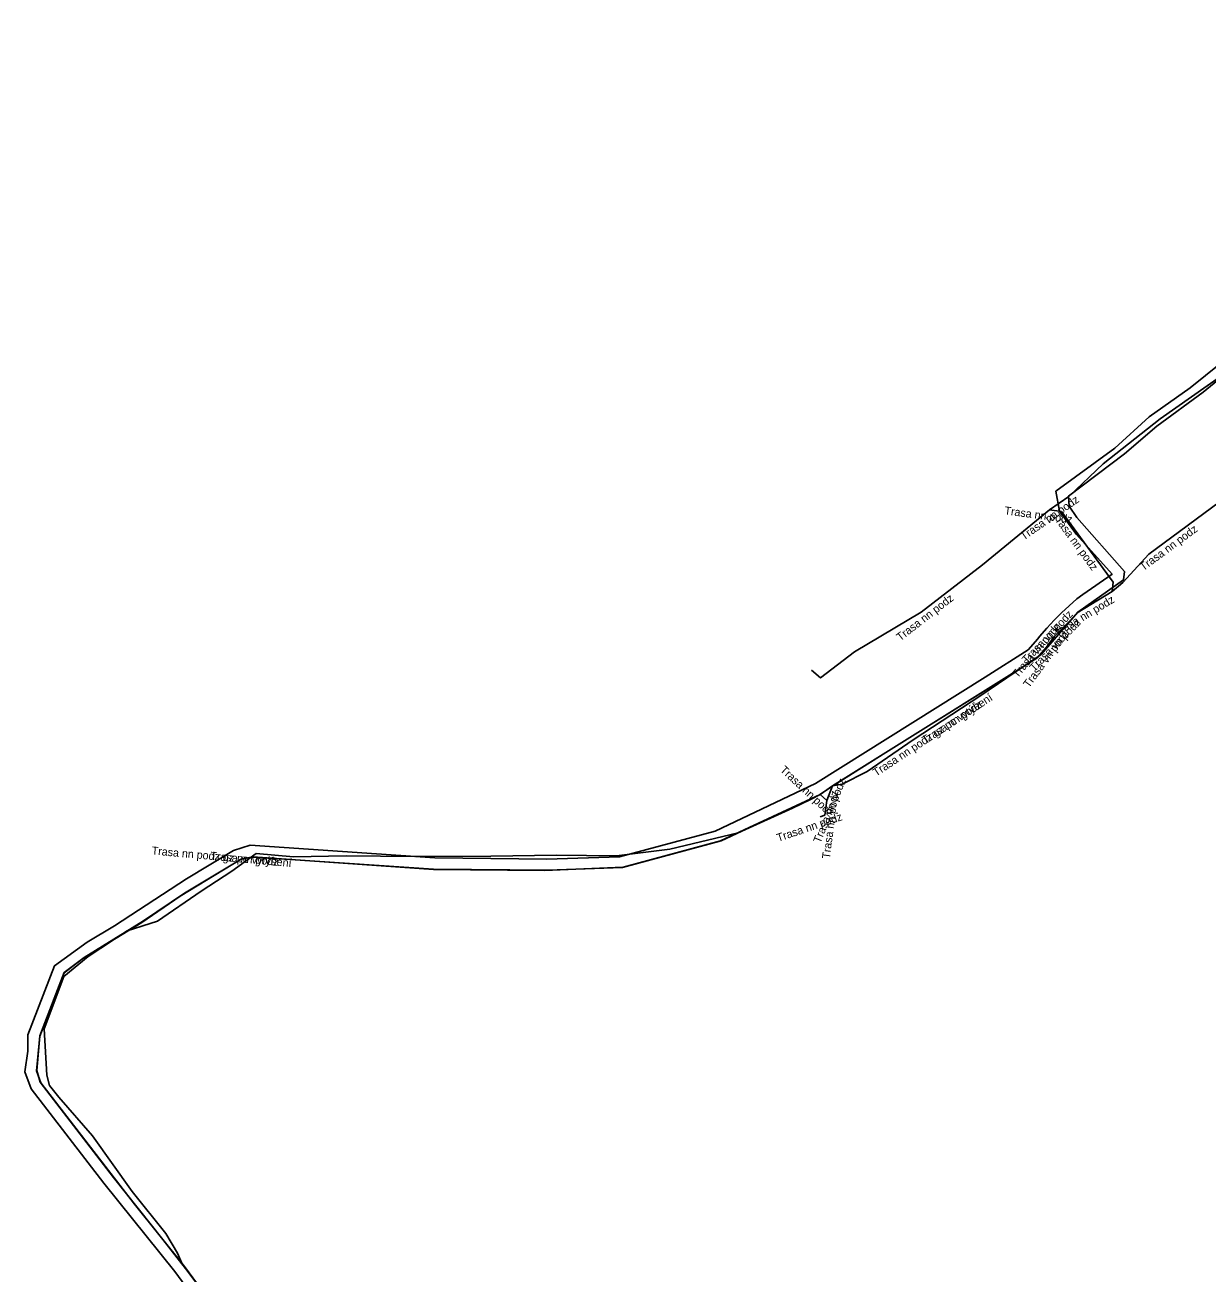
# Model space of a CAD drawing. Extents: x -703240 to -702678, y -1007635 to -1007322.
# Drawn here: x -702904.4 to -702830.5, y -1007513.3 to -1007435.3 of the extents above; entities that cross this region are included whole.
import ezdxf

# ---------------------------------------------------------------- set-up
doc = ezdxf.new("R2010")
doc.units = 0
for name, color, linetype in [('Popiskový text - Ostatní atributy Trasy', 7, 'Continuous'), ('Spojnice NN', 7, 'Continuous'), ('Spojnice VN', 7, 'Continuous')]:
    doc.layers.add(name, color=color, linetype=linetype)

msp = doc.modelspace()

# ---------------------------------------------------------------- linework, layer by layer
at = {"layer": 'Spojnice NN'}
for points in [[(-702839.14, -1007464.79), (-702836.99, -1007462.74), (-702833.42, -1007459.94), (-702829.52, -1007457.19), (-702825.59, -1007453.79), (-702823.26, -1007451.11), (-702819.97, -1007448.18), (-702814.78, -1007443.62), (-702812.71, -1007442.11), (-702810.87, -1007440.57), (-702807.36, -1007437.54), (-702804.792, -1007435.331)], [(-702839.14, -1007464.79), (-702836.99, -1007462.74), (-702833.42, -1007459.94), (-702829.52, -1007457.19), (-702825.59, -1007453.79), (-702823.26, -1007451.11), (-702819.97, -1007448.18), (-702814.78, -1007443.62), (-702812.71, -1007442.11), (-702810.87, -1007440.57), (-702807.36, -1007437.54), (-702804.792, -1007435.331)], [(-702836.43, -1007470.73), (-702835.75, -1007470.17), (-702834.13, -1007468.4), (-702829.26, -1007464.8), (-702827.98, -1007463.68)], [(-702840.34, -1007465.63), (-702839.14, -1007464.79)], [(-702840.34, -1007465.63), (-702844.53, -1007469.06), (-702848.35, -1007472.01), (-702852.53, -1007474.49), (-702854.65, -1007476.12), (-702855.22, -1007475.65)], [(-702839.6, -1007465.73), (-702840.34, -1007465.63)], [(-702836.43, -1007470.73), (-702836.36, -1007470.15), (-702839.6, -1007465.73)], [(-702838.62, -1007472.05), (-702836.43, -1007470.73)], [(-702853.89, -1007482.87), (-702853.3, -1007482.76), (-702851.73, -1007481.97), (-702848.86, -1007480), (-702844.63, -1007477.22), (-702840.87, -1007474.67), (-702838.568, -1007472.016)], [(-702853.89, -1007482.87), (-702853.3, -1007482.76), (-702851.73, -1007481.97), (-702848.86, -1007480), (-702844.63, -1007477.22), (-702840.87, -1007474.67), (-702838.568, -1007472.016)], [(-702854.26, -1007483.78), (-702853.89, -1007482.87)], [(-702894.55, -1007512.69), (-702894.82, -1007512.06), (-702895.56, -1007510.83), (-702897.66, -1007508.21), (-702900.14, -1007504.74), (-702902.23, -1007502.31), (-702902.82, -1007501.6), (-702902.99, -1007500.95), (-702903.16, -1007498.04), (-702901.92, -1007494.78), (-702900.4, -1007493.52), (-702897.98, -1007491.93), (-702896.07, -1007491.32), (-702893.35, -1007489.44), (-702891.44, -1007488.19), (-702889.91, -1007487.09), (-702887.58, -1007487.3), (-702884.28, -1007487.25), (-702880, -1007487.29), (-702875.24, -1007487.27), (-702871.14, -1007487.2), (-702867.4, -1007487.25), (-702864.06, -1007486.82), (-702859.79, -1007485.81), (-702856.4, -1007484.26), (-702855.28, -1007483.73), (-702854.67, -1007483.4)], [(-702894.55, -1007512.69), (-702894.82, -1007512.06), (-702895.56, -1007510.83), (-702897.66, -1007508.21), (-702900.14, -1007504.74), (-702902.23, -1007502.31), (-702902.82, -1007501.6), (-702902.99, -1007500.95), (-702903.16, -1007498.04), (-702901.92, -1007494.78), (-702900.4, -1007493.52), (-702897.98, -1007491.93), (-702896.07, -1007491.32), (-702893.35, -1007489.44), (-702891.44, -1007488.19), (-702889.91, -1007487.09), (-702887.58, -1007487.3), (-702884.28, -1007487.25), (-702880, -1007487.29), (-702875.24, -1007487.27), (-702871.14, -1007487.2), (-702867.4, -1007487.25), (-702864.06, -1007486.82), (-702859.79, -1007485.81), (-702856.4, -1007484.26), (-702855.28, -1007483.73), (-702854.67, -1007483.4)], [(-702854.67, -1007483.4), (-702854.26, -1007483.78)], [(-702854.26, -1007483.78), (-702854.375, -1007484.698)], [(-702854.661, -1007484.795), (-702854.375, -1007484.698)]]:
    msp.add_lwpolyline(points, dxfattribs=at)
at = {"layer": 'Spojnice VN'}
for points in [[(-702827.827, -1007455.01), (-702831.56, -1007458.012), (-702834.103, -1007459.821), (-702836.257, -1007461.777), (-702839.953, -1007464.459), (-702839.722, -1007465.716), (-702838.646, -1007467.157), (-702836.43, -1007469.652), (-702838.258, -1007470.92), (-702838.624, -1007471.186), (-702839.593, -1007472.052)], [(-702827.331, -1007455.484), (-702830.736, -1007458.277), (-702833.625, -1007460.39), (-702835.657, -1007462.134), (-702839.144, -1007464.761), (-702839.105, -1007465.389), (-702838.629, -1007466.1), (-702835.663, -1007469.469), (-702835.72, -1007470.002), (-702838.568, -1007472.016), (-702839.1, -1007472.57)], [(-702839.593, -1007472.052), (-702840.05, -1007472.519), (-702840.517, -1007473.013)], [(-702840.517, -1007473.013), (-702840.955, -1007473.529), (-702841.076, -1007473.679)], [(-702839.1, -1007472.57), (-702840.02, -1007473.52)], [(-702840.02, -1007473.52), (-702839.1, -1007472.57)], [(-702841.076, -1007473.679), (-702841.668, -1007474.363), (-702844.359, -1007476.086), (-702854.952, -1007482.726), (-702861.226, -1007485.69), (-702867.214, -1007487.307), (-702871.752, -1007487.458), (-702878.755, -1007487.363), (-702890.287, -1007486.584), (-702891.328, -1007486.908), (-702894.272, -1007488.676), (-702898.755, -1007491.604), (-702900.467, -1007492.628), (-702902.51, -1007494.113), (-702904.183, -1007498.427), (-702904.183, -1007499.436), (-702904.356, -1007500.731), (-702903.972, -1007501.796), (-702899.43, -1007507.686), (-702894.987, -1007513.213), (-702893.329, -1007515.479)], [(-702840.02, -1007473.52), (-702840.53, -1007474.21)], [(-702840.53, -1007474.21), (-702840.02, -1007473.52)], [(-702840.53, -1007474.21), (-702841.172, -1007474.915), (-702850.572, -1007480.791), (-702854.007, -1007482.956), (-702854.719, -1007483.432), (-702860.857, -1007486.301), (-702867.017, -1007487.966), (-702871.682, -1007488.146), (-702878.823, -1007488.079), (-702887.775, -1007487.471), (-702890.228, -1007487.319), (-702890.883, -1007487.472), (-702894.663, -1007489.77), (-702897.057, -1007491.404), (-702900.737, -1007493.661), (-702901.907, -1007494.55), (-702903.427, -1007498.513), (-702903.629, -1007500.665), (-702903.361, -1007501.422), (-702897.51, -1007509.006), (-702894.394, -1007512.891), (-702893.276, -1007514.395)], [(-702893.31, -1007514.37), (-702894.32, -1007513.02), (-702895.75, -1007511.22), (-702898.83, -1007507.33), (-702903.41, -1007501.39), (-702903.62, -1007500.66), (-702903.43, -1007498.49), (-702901.91, -1007494.54), (-702900.66, -1007493.6), (-702896.94, -1007491.3), (-702894.38, -1007489.58), (-702890.85, -1007487.45), (-702890.12, -1007487.31), (-702878.82, -1007488.1), (-702871.89, -1007488.15), (-702866.98, -1007487.95), (-702860.89, -1007486.31), (-702854.67, -1007483.4), (-702853.89, -1007482.87), (-702841.14, -1007474.9), (-702840.53, -1007474.21)]]:
    msp.add_lwpolyline(points, dxfattribs=at)

# ---------------------------------------------------------------- texts
at = {"layer": 'Popiskový text - Ostatní atributy Trasy'}
for s, rotation, p in [('Trasa nn podz', 34.99202, (-702841.946, -1007467.548)), ('Trasa nn podz', 352.30395, (-702843.177, -1007465.902)), ('Trasa nn podz', 306.2426, (-702840.193, -1007466.021)), ('Trasa nn podz', 36.47254, (-702834.475, -1007469.463)), ('Trasa nn podz', 37.67716, (-702849.665, -1007473.847)), ('Trasa nn podz', 31.07904, (-702839.886, -1007473.572)), ('Trasa vn podz', 46.60934, (-702841.749, -1007475.262)), ('Trasa vn podz', 49.67416, (-702842.339, -1007476.164)), ('Trasa vn podz', 45.9191, (-702841.283, -1007475.758)), ('Trasa vn podz', 45.9191, (-702841.283, -1007475.758)), ('Trasa vn podz', 53.53077, (-702841.623, -1007476.783)), ('Trasa vn podz', 53.53077, (-702841.623, -1007476.783)), ('Trasa nn podz gz po vytýèení', 33.31333, (-702851.172, -1007482.297)), ('Trasa nn podz', 33.31333, (-702848.092, -1007480.273)), ('Trasa nn podz', 317.17474, (-702857.216, -1007481.927)), ('Trasa nn podz', 67.87367, (-702854.658, -1007486.486)), ('Trasa nn podz', 82.85962, (-702854.064, -1007487.443)), ('Trasa nn podz', 18.73492, (-702857.291, -1007486.373)), ('Trasa nn podz gz po vytýèení', 354.84992, (-702896.455, -1007487.153)), ('Trasa nn podz', 354.84992, (-702892.784, -1007487.483))]:
    msp.add_text(s, height=0.5, rotation=rotation, dxfattribs=at).set_placement(p)

doc.saveas('drawing.dxf')
